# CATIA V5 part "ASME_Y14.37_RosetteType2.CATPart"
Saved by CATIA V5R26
Part number: 333X3333-303
Revision: --
Nomenclature: ASME_Y14.37_RosetteType2
Bounding box of the stored display mesh (mm): x -188.298 to 158.032, y -714.612 to 664.697, z 0 to 106.879
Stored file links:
  C:\Users\jvl2147\Documents\ASME Y14.37\Rosettes\PartExamples\ASME_Y14.37_RosetteType2.CATPart
  \\NW\Data\MSE-Composites\ASME Y14.37\ASME Y-14.37_COMPOSITES.CATMaterial
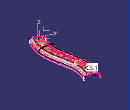
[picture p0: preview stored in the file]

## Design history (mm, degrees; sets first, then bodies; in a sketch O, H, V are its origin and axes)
AxisSystem1 "ROSETTE COORDINATE SYSTEM": origin (-72.9205, -637.9645, 93.98), X (0.5026, 0.8645, 0), Y (-0.8645, 0.5026, 0), Z (0, 0, 1)
CompParametersFeature1 "CATCoParametersFeatName": Value 0, Value 45, Value -45, Value 90
CompEOPGroupFeature1 "CATCoEOPGroupFeatName"
CompStacking1 "Stacking"
CompIsoThickAreasGroup1 "CATCoIsoThickAreasGroupFeatName": RefAddThickness 0
TTRSSet1
f4a2d38f3ddc11d3a929006094b99c4b_11 "CATTPSSet"
CompReviewTools1 "Review tools"
Set1 "CONSTRUCTION GEOMETRY"
  Set2 "CONSTRUCTION - LAMINATE REFERENCE SURFACE"
    Sketch1 on xy-plane, origin (0, 0, 0), H (1, 0, 0), V (0, 1, 0)
      spline S1 through (-79.505, -649.09) (21.2912, -260.3998) (-51.6257, 228.8061) (37.963, 602.845)
    Plane1: type Normal, Curve Sketch1, RefPoint vertex of Sketch1, Ratio 0
    Sketch2 on Plane1, origin (-464.3095, -417.3341, 0), H (-0.8566, 0.5159, 0), V (0, 0, 1)
      line L1 (-525.4052, 91.6386) -> (-373.0052, 91.6386)
      line L2 (-322.2052, 40.8386) -> (-322.2052, 0)
      line L3 (-576.2052, 0) -> (-576.2052, 40.8386)
      reference projected point E1 (-449.2052, 0) from vertex of Sketch1
      reference projected point E2 (-449.2052, 0) from vertex of Sketch1
      arc A1 centre (-373.0052, 40.8386) radius 50.8 from (-373.0052, 91.6386) to (-322.2052, 40.8386) cw
      arc A2 centre (-525.4052, 40.8386) radius 50.8 from (-576.2052, 40.8386) to (-525.4052, 91.6386) cw
      distance E1 L2 = 127
      distance E2 L3 = 127
      radius A1 = 50.8
      radius A2 = 50.8
      horizontal: L1 H
      vertical: L2 V, L3 V
      tangency: A1 L1, A1 L2, A2 L3, A2 L1
    Sweep1: type Unspec, Profile Sketch2, Guide Sketch1
  Set3 "CONSTRUCTION - PLIES EOPS"
    Plane2: type Normal, Curve Sketch1, RefPoint vertex of Sketch1, Ratio 0
    Plane3: type Normal, Curve Sketch1, RefPoint {point type OnCurve, Support Sketch1, Length 1118.262}, Ratio 0.99
    Plane4: type Normal, Curve Sketch1, Ratio 0.01
    Intersect1: ToIntersect1 Plane3, ToIntersect2 Sweep1
    Intersect2: ToIntersect1 Sweep1, ToIntersect2 Plane4
    Plane5: type Offset, RefPlane xy-plane, Offset 2.54
    Intersect3: ToIntersect1 Plane5, ToIntersect2 Join1
    Near1: MultiElement Intersect3, ReferenceElement edge of Sweep1
    Near2: MultiElement Intersect3, ReferenceElement edge of Sweep1
  Set4 "CONSTRUCTION - ROSETTE COORDINATE SYSTEM"
    Intersect4: ToIntersect1 Plane4, ToIntersect2 Project2
    Line1: type Tangency, RefPoint Intersect4, Curve Project2, Start 0, End 25.4
    Plane6: type Offset, RefPlane xy-plane, Offset 93.98
    Project1 "PROJECT": ToProject Sketch1, Support Join1, Direction xy-plane
  Set5 "CONSTRUCTION - ROSETTE TRANSFORMS"
    Line2 "Ply.1_Rosette_transfer_X": type Tangency, RefPoint {point type OnCurve, Support Project2, Length 288.56}, Curve Project2, Support Join1, Start 0, End 25.4
    Line3 "Ply.1_Rosette_transfer_X.Renamed": type Tangency, RefPoint {point type OnCurve, Support Project2, Length 536.186}, Curve Project2, Support Join1, Start 25.4, End 0
    Line4 "Ply.1_Rosette_transfer_X.Renamed": type Tangency, RefPoint {point type OnCurve, Support Project2, Length 783.62}, Curve Project2, Support Join1, Start 25.4, End 0
    Line5 "Ply.1_Rosette_transfer_X.Renamed": type Tangency, RefPoint {point type OnCurve, Support Project2, Length 1274.71}, Curve Project2, Support Join1, Start 25.4, End 0
    Line6 "Ply.1_Rosette_transfer_X.Renamed": type Tangency, RefPoint {point type OnCurve, Support Project2, Length 1017.245}, Curve Project2, Support Join1, Start 25.4, End 0
    AxisSystem2 "ROSETTE COORDINATE SYSTEM": origin (16.8931, -379.3831, 93.98), X (0.1242, 0.9923, 0), Y (-0.9923, 0.1242, 0), Z (0, 0, 1)
    AxisSystem3 "ROSETTE COORDINATE SYSTEM.Renamed": origin (7.1166, -132.8437, 93.98), X (-0.1632, 0.9866, 0), Y (-0.9866, -0.1632, 0), Z (0, 0, 1)
    AxisSystem4 "ROSETTE COORDINATE SYSTEM.Renamed1": origin (-38.9217, 110.2518, 93.98), X (-0.1571, 0.9876, 0), Y (-0.9876, -0.1571, 0), Z (0, 0, 1)
    AxisSystem5 "ROSETTE COORDINATE SYSTEM.Renamed2": origin (29.3229, 586.9432, 93.98), X (0.4677, 0.8839, 0), Y (-0.8839, 0.4677, 0), Z (0, 0, 1)
    AxisSystem6 "ROSETTE COORDINATE SYSTEM.Renamed3": origin (-47.995, 342.9553, 93.98), X (0.1137, 0.9935, 0), Y (-0.9935, 0.1137, 0), Z (0, 0, 1)
    Point1: type OnSurface, Support Join1, Length 362.156, Direction (-0.4364, -0.3881, 0.8118)
    Line7: type Normal, RefPoint Point1, RefSkin Join1, Start 254, End 0
  Plane7: type Offset, RefPlane YZ plane of AxisSystem2, Offset 0
Set6 "ENGINEERING GEOMETRY"
  Set7 "LAMINATE REFERENCE SURFACE"
    Join1 "LAMINATE REFERENCE SURFACE": Elements Sweep1
  Set8 "GUIDE CURVE - ZERO DEGREE ORIENTATION"
    Project2 "GUIDE CURVE - 0°": ToProject Sketch1, Support Plane6
Body1 (main body)
Body2 "-303"
  CompIsoThickAreasSolid1 "Area Solid.1": IsoAreasGroup CompIsoThickAreasGroup1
